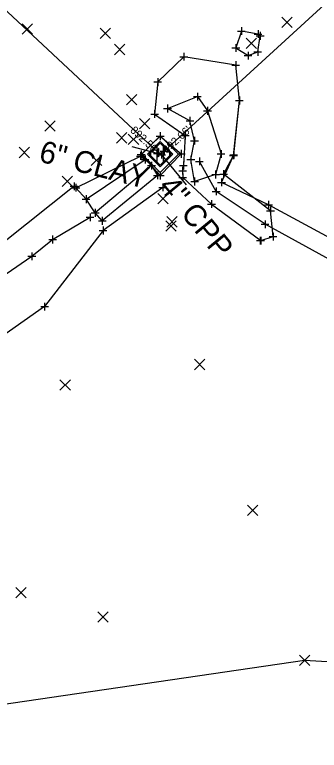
# Model space of a CAD drawing. Extents: x 236 to 155644, y 66 to 491728.
# Drawn here: x 147919.6 to 147958.6, y 487231.4 to 487325.4 of the extents above; entities that cross this region are included whole.
import ezdxf

# ---------------------------------------------------------------- set-up
doc = ezdxf.new("R2010")
doc.units = 0
for name, color, linetype in [('DR_X_Erosion_Control', 7, 'Continuous'), ('DR_X_Storm_Sewer', 7, 'Continuous'), ('DR_X_Text', 7, 'Continuous'), ('RD_X_Cells', 7, 'Continuous'), ('RD_X_Concrete_Pad', 7, 'Continuous'), ('RD_X_RR_Cells', 7, 'Continuous'), ('RW_X_CL', 7, 'Continuous'), ('RW_X_Esmt_LA', 7, 'Continuous'), ('SC_Scratch1', 7, 'Continuous'), ('SV_P_Mon_Cells_Set', 7, 'Continuous'), ('SV_X_Mon_Cells_Found', 7, 'Continuous'), ('SV_X_Shot_Marker', 7, 'Continuous'), ('SV_X_Terrain_Boundary', 7, 'Continuous')]:
    doc.layers.add(name, color=color, linetype=linetype)

msp = doc.modelspace()

# ---------------------------------------------------------------- linework, layer by layer
at = {"layer": 'DR_X_Erosion_Control'}
msp.add_lwpolyline([(147947.592, 487307.46), (147948.349, 487314.472), (147947.877, 487319.001), (147941.238, 487320.072), (147937.903, 487316.854), (147937.512, 487312.747), (147941.434, 487310.013), (147941.183, 487306.17), (147941.087, 487305.496), (147941.103, 487304.632), (147944.787, 487301.237), (147951.078, 487296.56), (147952.652, 487297.07), (147952.315, 487300.393), (147946.329, 487305.081)], close=True, dxfattribs=at)
at = {"layer": 'DR_X_Storm_Sewer'}
for p, q in [((147938.72, 487308.02), (148143.232, 487495.005)), ((147869.463, 487371.625), (147938.024, 487307.796)), ((147937.877, 487307.714), (147934.659, 487308.542)), ((147938.383, 487307.553), (147941.535, 487303.712))]:
    msp.add_line(p, q, dxfattribs=at)
at = {"layer": 'RD_X_Cells'}
for p, q in [((147948.6, 487323.862), (147948.6, 487322.862)), ((147950.731, 487323.47), (147950.731, 487322.47)), ((147948.1, 487323.362), (147949.1, 487323.362)), ((147948.6, 487323.362), (147948.6, 487323.362)), ((147950.231, 487322.97), (147951.231, 487322.97)), ((147950.503, 487322.751), (147951.503, 487322.751)), ((147950.731, 487322.97), (147950.731, 487322.97)), ((147951.003, 487323.251), (147951.003, 487322.251)), ((147951.003, 487322.751), (147951.003, 487322.751)), ((147947.895, 487321.694), (147947.895, 487320.694)), ((147947.395, 487321.194), (147948.395, 487321.194)), ((147947.895, 487321.194), (147947.895, 487321.194)), ((147949.459, 487320.713), (147949.459, 487319.713)), ((147950.185, 487320.704), (147951.185, 487320.704)), ((147950.685, 487321.204), (147950.685, 487320.204)), ((147950.685, 487320.704), (147950.685, 487320.704)), ((147940.738, 487320.072), (147941.738, 487320.072)), ((147940.738, 487320.072), (147941.738, 487320.072)), ((147941.238, 487320.572), (147941.238, 487319.572)), ((147941.238, 487320.572), (147941.238, 487319.572)), ((147941.238, 487320.072), (147941.238, 487320.072)), ((147941.238, 487320.072), (147941.238, 487320.072)), ((147948.959, 487320.213), (147949.959, 487320.213)), ((147949.459, 487320.213), (147949.459, 487320.213)), ((147947.377, 487319.001), (147948.377, 487319.001)), ((147947.377, 487319.001), (147948.377, 487319.001)), ((147947.877, 487319.501), (147947.877, 487318.501)), ((147947.877, 487319.501), (147947.877, 487318.501)), ((147947.877, 487319.001), (147947.877, 487319.001)), ((147947.877, 487319.001), (147947.877, 487319.001)), ((147937.403, 487316.854), (147938.403, 487316.854)), ((147937.403, 487316.854), (147938.403, 487316.854)), ((147937.903, 487317.354), (147937.903, 487316.354)), ((147937.903, 487317.354), (147937.903, 487316.354)), ((147937.903, 487316.854), (147937.903, 487316.854)), ((147937.903, 487316.854), (147937.903, 487316.854)), ((147942.476, 487314.973), (147943.476, 487314.973)), ((147942.976, 487315.473), (147942.976, 487314.473)), ((147942.976, 487314.973), (147942.976, 487314.973)), ((147948.349, 487314.972), (147948.349, 487313.972)), ((147948.349, 487314.972), (147948.349, 487313.972)), ((147947.849, 487314.472), (147948.849, 487314.472)), ((147947.849, 487314.472), (147948.849, 487314.472)), ((147948.349, 487314.472), (147948.349, 487314.472)), ((147948.349, 487314.472), (147948.349, 487314.472)), ((147937.512, 487313.247), (147937.512, 487312.247)), ((147937.512, 487313.247), (147937.512, 487312.247)), ((147938.664, 487313.458), (147939.664, 487313.458)), ((147939.164, 487313.958), (147939.164, 487312.958)), ((147939.164, 487313.458), (147939.164, 487313.458)), ((147943.761, 487313.158), (147944.761, 487313.158)), ((147944.261, 487313.658), (147944.261, 487312.658)), ((147944.261, 487313.158), (147944.261, 487313.158)), ((147937.012, 487312.747), (147938.012, 487312.747)), ((147937.012, 487312.747), (147938.012, 487312.747)), ((147937.512, 487312.747), (147937.512, 487312.747)), ((147937.512, 487312.747), (147937.512, 487312.747)), ((147942.031, 487312.381), (147942.031, 487311.381)), ((147941.531, 487311.881), (147942.531, 487311.881)), ((147942.031, 487311.881), (147942.031, 487311.881)), ((147938.222, 487310.418), (147938.222, 487309.418)), ((147941.434, 487310.513), (147941.434, 487309.513)), ((147941.434, 487310.513), (147941.434, 487309.513)), ((147937.722, 487309.918), (147938.722, 487309.918)), ((147938.222, 487309.918), (147938.222, 487309.918)), ((147940.934, 487310.013), (147941.934, 487310.013)), ((147940.934, 487310.013), (147941.934, 487310.013)), ((147941.434, 487310.013), (147941.434, 487310.013)), ((147941.434, 487310.013), (147941.434, 487310.013)), ((147942.099, 487309.337), (147943.099, 487309.337)), ((147942.599, 487309.837), (147942.599, 487308.837)), ((147942.599, 487309.337), (147942.599, 487309.337)), ((147935.296, 487307.567), (147936.296, 487307.567)), ((147935.714, 487307.875), (147935.714, 487306.875)), ((147935.796, 487308.067), (147935.796, 487307.067)), ((147935.796, 487307.567), (147935.796, 487307.567)), ((147936.283, 487307.441), (147936.283, 487306.441)), ((147940.418, 487307.652), (147941.418, 487307.652)), ((147940.918, 487308.152), (147940.918, 487307.152)), ((147940.918, 487307.652), (147940.918, 487307.652)), ((147945.507, 487307.64), (147946.507, 487307.64)), ((147946.007, 487308.14), (147946.007, 487307.14)), ((147946.007, 487307.64), (147946.007, 487307.64)), ((147947.092, 487307.46), (147948.092, 487307.46)), ((147947.125, 487307.542), (147948.125, 487307.542)), ((147947.592, 487307.96), (147947.592, 487306.96)), ((147947.592, 487307.46), (147947.592, 487307.46)), ((147947.625, 487308.042), (147947.625, 487307.042)), ((147947.625, 487307.542), (147947.625, 487307.542)), ((147935.214, 487307.375), (147936.214, 487307.375)), ((147935.714, 487307.375), (147935.714, 487307.375)), ((147935.783, 487306.941), (147936.783, 487306.941)), ((147936.283, 487306.941), (147936.283, 487306.941)), ((147937.11, 487306.653), (147937.11, 487305.653)), ((147941.183, 487306.67), (147941.183, 487305.67)), ((147941.183, 487306.67), (147941.183, 487305.67)), ((147941.649, 487306.917), (147942.649, 487306.917)), ((147942.149, 487307.417), (147942.149, 487306.417)), ((147942.149, 487306.917), (147942.149, 487306.917)), ((147942.738, 487306.697), (147943.738, 487306.697)), ((147943.238, 487307.197), (147943.238, 487306.197)), ((147943.238, 487306.697), (147943.238, 487306.697)), ((147936.61, 487306.153), (147937.61, 487306.153)), ((147937.11, 487306.153), (147937.11, 487306.153)), ((147940.683, 487306.17), (147941.683, 487306.17)), ((147940.683, 487306.17), (147941.683, 487306.17)), ((147941.087, 487305.996), (147941.087, 487304.996)), ((147941.087, 487305.996), (147941.087, 487304.996)), ((147941.183, 487306.17), (147941.183, 487306.17)), ((147941.183, 487306.17), (147941.183, 487306.17)), ((147946.329, 487305.581), (147946.329, 487304.581)), ((147937.374, 487304.906), (147938.374, 487304.906)), ((147937.722, 487304.889), (147938.722, 487304.889)), ((147937.874, 487305.406), (147937.874, 487304.406)), ((147937.874, 487304.906), (147937.874, 487304.906)), ((147938.222, 487305.389), (147938.222, 487304.389)), ((147938.222, 487304.889), (147938.222, 487304.889)), ((147940.587, 487305.496), (147941.587, 487305.496)), ((147940.587, 487305.496), (147941.587, 487305.496)), ((147940.603, 487304.632), (147941.603, 487304.632)), ((147940.603, 487304.632), (147941.603, 487304.632)), ((147941.087, 487305.496), (147941.087, 487305.496)), ((147941.087, 487305.496), (147941.087, 487305.496)), ((147941.103, 487305.132), (147941.103, 487304.132)), ((147941.103, 487305.132), (147941.103, 487304.132)), ((147941.103, 487304.632), (147941.103, 487304.632)), ((147941.103, 487304.632), (147941.103, 487304.632)), ((147942.623, 487304.617), (147942.623, 487303.617)), ((147944.806, 487305.013), (147945.806, 487305.013)), ((147945.306, 487305.513), (147945.306, 487304.513)), ((147945.306, 487305.013), (147945.306, 487305.013)), ((147945.829, 487305.081), (147946.829, 487305.081)), ((147946.329, 487305.081), (147946.329, 487305.081)), ((147927.214, 487304.008), (147927.214, 487303.008)), ((147927.435, 487303.833), (147927.435, 487302.833)), ((147938.545, 487303.866), (147938.545, 487302.866)), ((147942.123, 487304.117), (147943.123, 487304.117)), ((147942.623, 487304.117), (147942.623, 487304.117)), ((147945.561, 487304.009), (147946.561, 487304.009)), ((147946.061, 487304.509), (147946.061, 487303.509)), ((147946.061, 487304.009), (147946.061, 487304.009)), ((147926.714, 487303.508), (147927.714, 487303.508)), ((147926.935, 487303.333), (147927.935, 487303.333)), ((147927.214, 487303.508), (147927.214, 487303.508)), ((147927.435, 487303.333), (147927.435, 487303.333)), ((147938.045, 487303.366), (147939.045, 487303.366)), ((147938.545, 487303.366), (147938.545, 487303.366)), ((147944.874, 487302.862), (147945.874, 487302.862)), ((147945.374, 487303.362), (147945.374, 487302.362)), ((147945.374, 487302.862), (147945.374, 487302.862)), ((147928.249, 487301.861), (147929.249, 487301.861)), ((147928.749, 487302.361), (147928.749, 487301.361)), ((147928.749, 487301.861), (147928.749, 487301.861)), ((147944.287, 487301.237), (147945.287, 487301.237)), ((147944.287, 487301.237), (147945.287, 487301.237)), ((147944.787, 487301.737), (147944.787, 487300.737)), ((147944.787, 487301.737), (147944.787, 487300.737)), ((147944.787, 487301.237), (147944.787, 487301.237)), ((147944.787, 487301.237), (147944.787, 487301.237)), ((147951.562, 487301.149), (147952.562, 487301.149)), ((147952.062, 487301.649), (147952.062, 487300.649)), ((147952.062, 487301.149), (147952.062, 487301.149)), ((147952.315, 487300.893), (147952.315, 487299.893)), ((147929.252, 487300.049), (147929.252, 487299.049)), ((147929.401, 487300.112), (147930.401, 487300.112)), ((147929.901, 487300.612), (147929.901, 487299.612)), ((147929.901, 487300.112), (147929.901, 487300.112)), ((147951.815, 487300.393), (147952.815, 487300.393)), ((147952.315, 487300.393), (147952.315, 487300.393)), ((147928.752, 487299.549), (147929.752, 487299.549)), ((147929.252, 487299.549), (147929.252, 487299.549)), ((147930.321, 487299.085), (147931.321, 487299.085)), ((147930.821, 487299.585), (147930.821, 487298.585)), ((147930.821, 487299.085), (147930.821, 487299.085)), ((147951.63, 487299.15), (147951.63, 487298.15)), ((147930.92, 487298.362), (147930.92, 487297.362)), ((147951.13, 487298.65), (147952.13, 487298.65)), ((147951.63, 487298.65), (147951.63, 487298.65)), ((147924.471, 487297.199), (147924.471, 487296.199)), ((147930.42, 487297.862), (147931.42, 487297.862)), ((147930.92, 487297.862), (147930.92, 487297.862)), ((147952.652, 487297.57), (147952.652, 487296.57)), ((147923.971, 487296.699), (147924.971, 487296.699)), ((147924.471, 487296.699), (147924.471, 487296.699)), ((147950.514, 487296.565), (147951.514, 487296.565)), ((147950.578, 487296.56), (147951.578, 487296.56)), ((147950.578, 487296.56), (147951.578, 487296.56)), ((147951.014, 487297.065), (147951.014, 487296.065)), ((147951.014, 487296.565), (147951.014, 487296.565)), ((147951.078, 487297.06), (147951.078, 487296.06)), ((147951.078, 487297.06), (147951.078, 487296.06)), ((147951.078, 487296.56), (147951.078, 487296.56)), ((147951.078, 487296.56), (147951.078, 487296.56)), ((147952.152, 487297.07), (147953.152, 487297.07)), ((147952.652, 487297.07), (147952.652, 487297.07)), ((147921.31, 487294.565), (147922.31, 487294.565)), ((147921.81, 487295.065), (147921.81, 487294.065)), ((147921.81, 487294.565), (147921.81, 487294.565)), ((147923.45, 487288.621), (147923.45, 487287.621)), ((147922.95, 487288.121), (147923.95, 487288.121)), ((147923.45, 487288.121), (147923.45, 487288.121))]:
    msp.add_line(p, q, dxfattribs=at)
at = {"layer": 'RD_X_Concrete_Pad'}
for points in [[(147938.222, 487304.889), (147935.796, 487307.567), (147938.222, 487309.918), (147940.918, 487307.652)], [(147937.874, 487304.906), (147930.821, 487299.085), (147929.901, 487300.112), (147928.749, 487301.861), (147927.435, 487303.333), (147935.714, 487307.375), (147936.283, 487306.941), (147937.11, 487306.153)]]:
    msp.add_lwpolyline(points, close=True, dxfattribs=at)
at = {"layer": 'RD_X_RR_Cells'}
for p, q in [((147938.72, 487308.52), (147938.72, 487307.52)), ((147937.377, 487307.714), (147938.377, 487307.714)), ((147937.524, 487307.796), (147938.524, 487307.796)), ((147937.877, 487308.214), (147937.877, 487307.214)), ((147937.877, 487307.714), (147937.877, 487307.714)), ((147937.883, 487307.553), (147938.883, 487307.553)), ((147938.024, 487308.296), (147938.024, 487307.296)), ((147938.024, 487307.796), (147938.024, 487307.796)), ((147938.22, 487308.02), (147939.22, 487308.02)), ((147938.383, 487308.053), (147938.383, 487307.053)), ((147938.383, 487307.553), (147938.383, 487307.553)), ((147938.72, 487308.02), (147938.72, 487308.02))]:
    msp.add_line(p, q, dxfattribs=at)
at = {"layer": 'RW_X_CL'}
msp.add_lwpolyline([(147993.477, 487240.71), (147985.953, 487262.65), (147972.85, 487284.07), (147964.592, 487291.568), (147951.63, 487298.65), (147945.374, 487302.862), (147943.238, 487306.697)], dxfattribs=at)
at = {"layer": 'RW_X_Esmt_LA'}
for p, q in [((147928.749, 487301.861), (147936.283, 487306.941)), ((147937.11, 487306.153), (147929.901, 487300.112))]:
    msp.add_line(p, q, dxfattribs=at)
for points in [[(147951.003, 487322.751), (147950.731, 487322.97), (147948.6, 487323.362), (147947.895, 487321.194), (147949.459, 487320.213), (147950.685, 487320.704)], [(147942.599, 487309.337), (147942.031, 487311.881), (147939.164, 487313.458), (147942.976, 487314.973), (147944.261, 487313.158), (147946.007, 487307.64), (147945.306, 487305.013), (147942.623, 487304.117), (147942.149, 487306.917)]]:
    msp.add_lwpolyline(points, close=True, dxfattribs=at)
for points in [[(147999.435, 487244.162), (147990.463, 487265.187), (147974.41, 487285.384), (147965.796, 487293.715), (147952.062, 487301.149), (147946.061, 487304.009), (147947.625, 487307.542), (147948.349, 487314.472), (147947.877, 487319.001), (147941.238, 487320.072), (147937.903, 487316.854), (147937.512, 487312.747), (147941.434, 487310.013), (147941.183, 487306.17), (147941.087, 487305.496), (147941.103, 487304.632), (147944.787, 487301.237), (147951.078, 487296.56), (147951.014, 487296.565)], [(147938.545, 487303.366), (147930.92, 487297.862), (147923.45, 487288.121), (147909.234, 487278.164), (147890.794, 487268.463), (147877.67, 487260.234), (147864.156, 487251.641), (147851.684, 487241.661), (147841.734, 487234.036), (147825.163, 487223.052), (147819.865, 487218.992), (147803.356, 487208.111), (147784.792, 487194.504), (147768.135, 487180.355), (147750.585, 487165.19), (147730.728, 487148.687)], [(147927.214, 487303.508), (147918.19, 487296.309), (147902.655, 487286.655), (147888.668, 487276.476), (147875.341, 487268.358), (147858.926, 487258.157)], [(147724.109, 487154.637), (147735.263, 487162.985), (147750.185, 487173.765), (147770.435, 487189.88), (147784.894, 487202.44), (147807.347, 487217.595), (147820.509, 487225.966), (147840.533, 487238.832), (147853.917, 487249.677), (147868.861, 487260.423), (147869.372, 487261.443), (147881.249, 487268.439), (147896.113, 487277.161), (147909.958, 487286.121), (147915.209, 487290.069), (147921.81, 487294.565), (147924.471, 487296.699), (147929.252, 487299.549)]]:
    msp.add_lwpolyline(points, dxfattribs=at)
at = {"layer": 'SV_P_Mon_Cells_Set'}
for p, q in [((147953.781, 487323.798), (147955.114, 487325.133)), ((147953.781, 487325.133), (147955.114, 487323.798)), ((147920.566, 487322.964), (147921.899, 487324.299)), ((147920.566, 487324.299), (147921.899, 487322.964)), ((147930.537, 487322.403), (147931.87, 487323.738)), ((147930.537, 487323.738), (147931.87, 487322.403)), ((147949.212, 487321.132), (147950.545, 487322.467)), ((147949.212, 487322.467), (147950.545, 487321.132)), ((147932.373, 487320.336), (147933.706, 487321.671)), ((147932.373, 487321.671), (147933.706, 487320.336)), ((147933.925, 487313.929), (147935.258, 487315.264)), ((147933.925, 487315.264), (147935.258, 487313.929)), ((147935.569, 487310.848), (147936.902, 487312.183)), ((147935.569, 487312.183), (147936.902, 487310.848)), ((147923.482, 487310.551), (147924.815, 487311.886)), ((147923.482, 487311.886), (147924.815, 487310.551)), ((147932.635, 487309.043), (147933.969, 487310.378)), ((147932.635, 487310.378), (147933.969, 487309.043)), ((147934.148, 487308.852), (147935.481, 487310.187)), ((147934.148, 487310.187), (147935.481, 487308.852)), ((147920.184, 487307.167), (147921.517, 487308.502)), ((147920.184, 487308.502), (147921.517, 487307.167)), ((147929.411, 487306.157), (147930.745, 487307.492)), ((147929.411, 487307.492), (147930.745, 487306.157)), ((147925.68, 487303.466), (147927.013, 487304.801)), ((147925.68, 487304.801), (147927.013, 487303.466)), ((147937.921, 487301.248), (147939.254, 487302.583)), ((147937.921, 487302.583), (147939.254, 487301.248)), ((147938.933, 487297.771), (147940.266, 487299.106)), ((147938.933, 487299.106), (147940.266, 487297.771)), ((147939.062, 487298.299), (147940.396, 487299.634)), ((147939.062, 487299.634), (147940.396, 487298.299)), ((147942.597, 487280.064), (147943.93, 487281.399)), ((147942.597, 487281.399), (147943.93, 487280.064)), ((147925.415, 487277.43), (147926.749, 487278.765)), ((147925.415, 487278.765), (147926.749, 487277.43)), ((147949.389, 487261.416), (147950.722, 487262.751)), ((147949.389, 487262.751), (147950.722, 487261.416)), ((147919.76, 487250.876), (147921.093, 487252.211)), ((147919.76, 487252.211), (147921.093, 487250.876)), ((147930.242, 487247.776), (147931.576, 487249.111)), ((147930.242, 487249.111), (147931.576, 487247.776)), ((147956.016, 487242.237), (147957.35, 487243.573)), ((147956.016, 487243.573), (147957.35, 487242.237))]:
    msp.add_line(p, q, dxfattribs=at)
at = {"layer": 'SV_X_Mon_Cells_Found'}
for p, q in [((147937.844, 487306.378), (147937.85, 487308.865)), ((147938.644, 487306.422), (147938.65, 487308.817)), ((147937.046, 487307.18), (147937.048, 487308.067)), ((147939.446, 487307.22), (147939.448, 487308.015))]:
    msp.add_line(p, q, dxfattribs=at)
for points in [[(147935.867, 487307.626), (147938.23, 487309.978), (147940.581, 487307.615), (147938.218, 487305.263)], [(147936.604, 487307.624), (147938.228, 487309.241), (147939.844, 487307.617), (147938.22, 487306)], [(147936.81, 487307.624), (147938.227, 487309.035), (147939.638, 487307.617), (147938.221, 487306.206)]]:
    msp.add_lwpolyline(points, close=True, dxfattribs=at)
at = {"layer": 'SV_X_Shot_Marker'}
for p, q in [((147937.048, 487308.802), (147937.048, 487308.802)), ((147937.519, 487308.329), (147937.519, 487308.329)), ((147938.224, 487307.62), (147938.224, 487307.62)), ((147938.224, 487307.62), (147938.224, 487307.62)), ((147938.224, 487307.62), (147938.224, 487307.62)), ((147938.933, 487308.326), (147938.933, 487308.326)), ((147937.515, 487306.915), (147937.515, 487306.915)), ((147938.929, 487306.912), (147938.929, 487306.912)), ((147939.4, 487306.439), (147939.4, 487306.439))]:
    msp.add_line(p, q, dxfattribs=at)
at = {"layer": 'SV_X_Terrain_Boundary'}
msp.add_lwpolyline([(147857.999, 487228.49), (147956.683, 487242.905), (147993.477, 487240.748), (148012.525, 487250.314), (148040.014, 487254.426), (148050.677, 487271.169), (148065.875, 487315.674), (148068.205, 487324.164), (148070.955, 487348.22), (148109.636, 487419.64), (148166.528, 487492.317), (148219.311, 487546.273), (148225.476, 487568.959), (148188.759, 487579.337), (148179.33, 487583.758), (148163.974, 487583.534), (148146.569, 487569.782), (148137.137, 487554.386), (148072.502, 487503.575), (148039.55, 487515.088), (148012.45, 487489.946), (147979.894, 487457.95), (147923.37, 487432.953), (147880.566, 487395.981)], dxfattribs=at)

# ---------------------------------------------------------------- texts
at = {"layer": 'DR_X_Text'}
for s, rotation, p in [('6" CLAY', 345.56937, (147922.572, 487306.715)), ('4" CPP', 309.37738, (147937.916, 487303.411))]:
    msp.add_text(s, height=2.8, rotation=rotation, dxfattribs=at).set_placement(p)
at = {"layer": 'SC_Scratch1'}
for s, rotation, p in [("892.06'", 42.43654, (147939.057, 487307.651)), ("892.56'", 317.04698, (147934.318, 487310.563))]:
    msp.add_text(s, height=1, rotation=rotation, dxfattribs=at).set_placement(p)

doc.saveas('drawing.dxf')
